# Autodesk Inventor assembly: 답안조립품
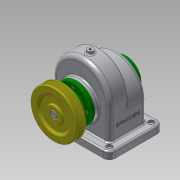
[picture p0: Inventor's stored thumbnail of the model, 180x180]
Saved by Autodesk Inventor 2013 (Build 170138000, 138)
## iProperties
Created: 2017-11
Part Number: 답안조립품
Document SubType Name: Assembly
Designer: Administrator
Author: Administrator
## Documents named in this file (14)
- C:\Users\Administrator\Desktop\471107V1037\답안조립품.iam
- C:\Users\Administrator\Desktop\471107V1037\V-벨트풀리.ipt
- C:\Users\Administrator\Desktop\471107V1037\뒤커버.ipt
- C:\Users\Administrator\Desktop\471107V1037\멈춤나사 - M4 x 10.ipt
- 멈춤나사 - M4 x 10.ipt
- C:\Users\Administrator\Desktop\471107V1037\베어링 6002.ipt
- C:\Users\Administrator\Desktop\471107V1037\본체.ipt
- C:\Users\Administrator\Desktop\471107V1037\볼트 M3 x 8.ipt
- C:\Users\Administrator\Desktop\471107V1037\스퍼기어.ipt
- C:\Users\Administrator\Desktop\471107V1037\앞커버.ipt
- C:\Users\Administrator\Desktop\471107V1037\오일 실 15 30 7.ipt
- C:\Users\Administrator\Desktop\471107V1037\축.ipt
- C:\Users\Administrator\Desktop\471107V1037\키 - 5 x 5 x 18.ipt
- C:\Users\Administrator\Desktop\471107V1037\키 - 6 x 6 x 22.ipt
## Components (1 placed, 1 different names)
1. V-벨트풀리:1 — 플러쉬:1
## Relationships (1: Flush 1)
- 플러쉬:1 [Flush]: V-벨트풀리:1
